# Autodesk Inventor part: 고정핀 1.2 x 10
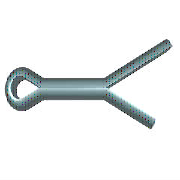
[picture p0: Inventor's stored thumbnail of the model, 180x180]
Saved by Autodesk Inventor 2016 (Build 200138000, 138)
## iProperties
IsCustomPart: 1
Created: 2012-02
Part Number: 고정핀 1.2 x 10
Material: 강철
Description: 분할 핀
Document SubType Name: Modeling
Standard: ISO 1234
Designer: test
Standard Revision: Second edition 1997-11-01
Standards Organization: ISO
Language: ko-KR
Size Designation: 1.2 x 10
Categories: <MemberInstance><Categories><Category DisplayName="조임쇠" InternalName="e4da775c-781d-43d5-af7c-5136215cf5a6" Mnemonic="FSTN"><Category DisplayName="핀" InternalNa
Density: 7.85 g/cm^3
Appearance: 파란색 - 벽 페인트 - 광택
Author: test
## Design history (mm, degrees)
sketch "스케치1"
  geometry: L1 (0, 0.5)-(5, 0.5); L2 (0, -0.5)-(5, -0.5); L3 (5, 0.5)-(10, 2.416); L4 (10, 2.416)-(10.167, 1.98); L5 (10.167, 1.98)-(5, 0); L6 (5, 0)-(12.667, -2.937); L7 (12.667, -2.937)-(12.5, -3.373); L8 (12.5, -3.373)-(5, -0.5); L9 (0, 0)-(-1.875, -0.484); L10 (0, 0)-(-1.875, 0.484); L11 (0, 0.5)-(0, -0.5); L12 (0, 0.5)-(-1.742, 0.966); L13 (0, -0.5)-(-1.742, -0.966); L14 (-3, 0)-(5, 0); L15 (5, 0.5)-(5, -0.5); A1 r 1 centre (-2, 0) between (-1.742, 0.966) and (-1.742, -0.966); A2 r 0.5 centre (-2, 0) between (-1.875, 0.484) and (-1.875, -0.484); 1 further point
  constraints: 30 end point, 5 point on circle, 4 parallel, 4 perpendicular, 4 point on line, 4 tangent, 2 centre point, 2 midpoint, 1 coincident, 1 horizontal
  dimensions: "d0" = 5 distance of L1.start L1.end (= MSIAB); "d1" = 10 horizontal distance of L1.start L3.end (= SNLG); "d2" = 159.037 deg angle of L1 L3; "d3" = 159.037 deg angle of L2 L8; "d4" = 2.5 horizontal distance of L3.end L7.end (= LGDIF); "d5" = 0.5 radius of A2 (= -0.5 x SNND1 + 0.5 x KBR); "d6" = 1 radius of A1 (= 0.5 x KBR); "d7" = 0.5 distance from line of L1 L9.start (= 0.5 x SNND1); "d8" = 0.5 distance between parallel lines of L2 L14 (= 0.5 x SNND1); "d9" = 2 distance from line of L11 A1.centre (= KOL - 0.5 x KBR)
extrude "본체" new body sketch "스케치1" stored distance "d10" = 1 (= SNND1); taper "d11" = 0 deg
workaxis "Work Axis1"
workplane "Work Plane1"
workplane "Work Plane3"
body "Solid1"
fillet "모깎기" dims "d12" = 0.35 (= 0.35 x SNND1)
other parameters: "SNND" = 1.2 [user parameter], "SNLG" = 10 [user parameter; used in 1 equation term], "SNND1" = 1 [user parameter; used in 5 equation terms], "KBR" = 2 [user parameter; used in 3 equation terms], "KOL" = 3 [user parameter; used in 1 equation term], "LGDIF" = 2.5 [user parameter; used in 1 equation term], "MSIAB" = 5 [user parameter; used in 1 equation term], "d15" = 0, "d16" = 0, "d17" = 0, "NNDMAX" = 5.5 [user parameter], "DSH" = 2.6 [user parameter], "NNDMIN" = 4.5 [user parameter]
